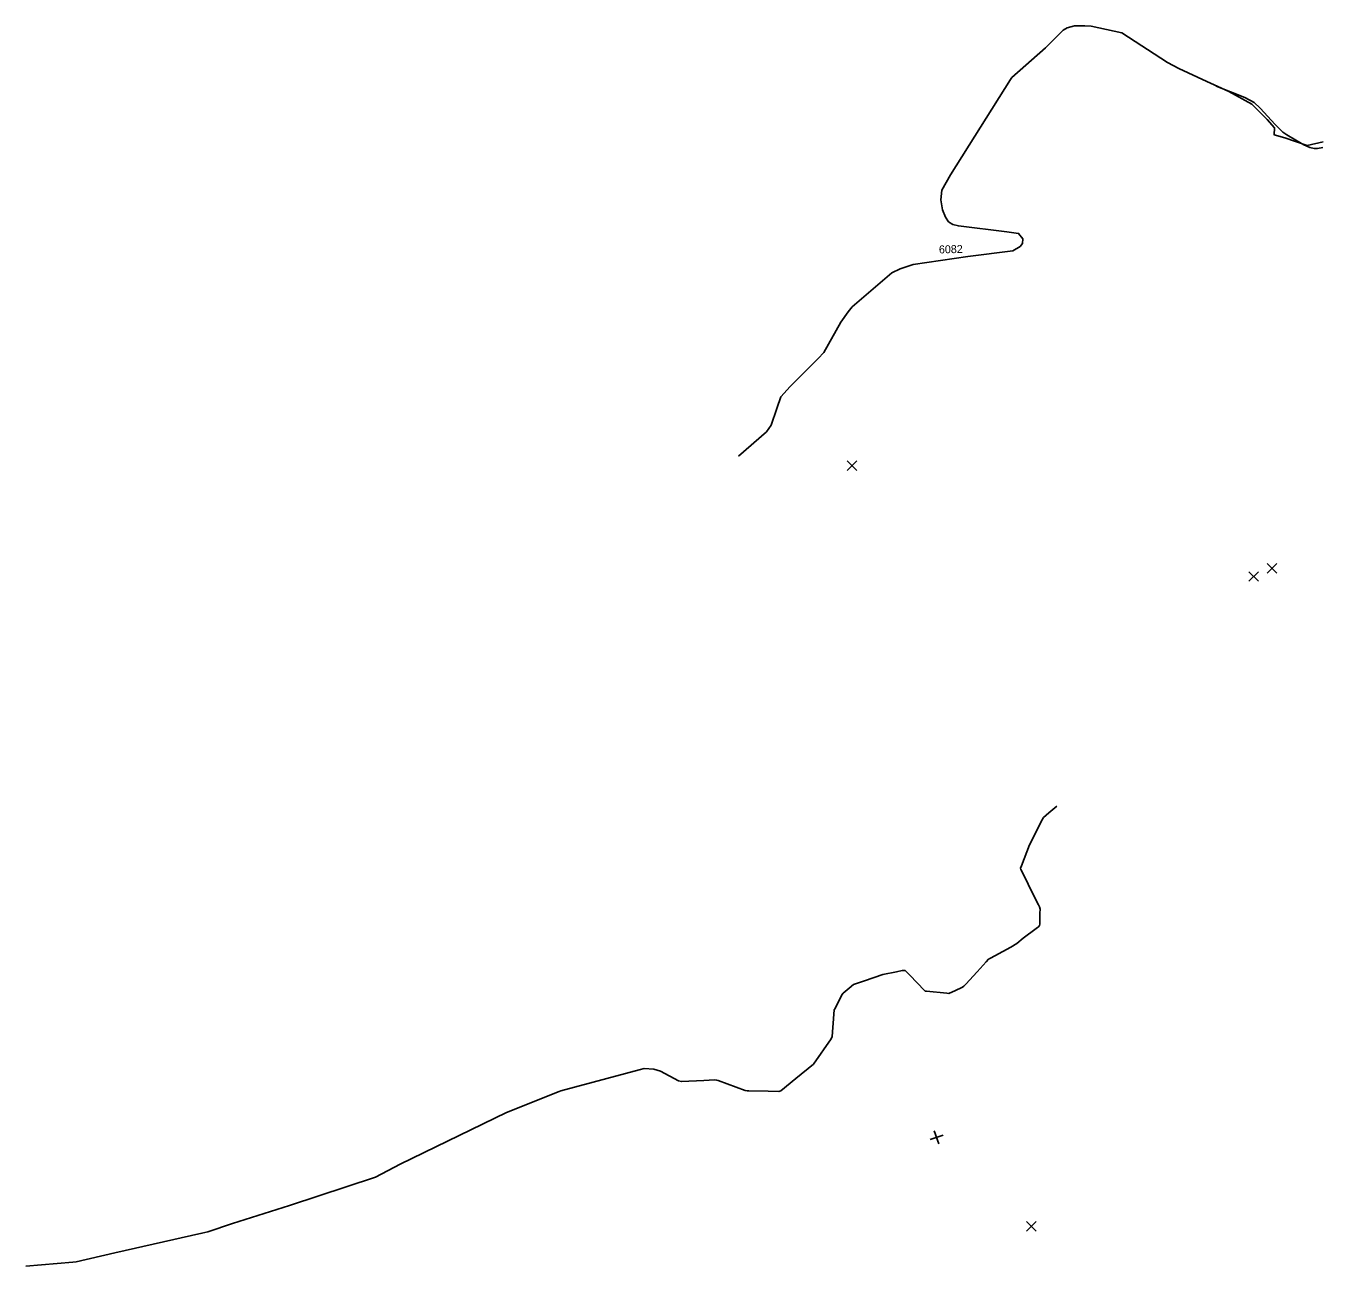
# Model space of a CAD drawing. Extents: x -446895 to -440760, y -1145420 to -1127323.
# Drawn here: x -444276 to -442655, y -1133374 to -1131824 of the extents above; entities that cross this region are included whole.
import ezdxf

# ---------------------------------------------------------------- set-up
doc = ezdxf.new("R2010")
doc.units = 0
for name, color, linetype in [('PLN_plynovod_L', 7, 'Continuous'), ('Vrstva 12', 7, 'Continuous'), ('Vrstva 200', 7, 'Continuous')]:
    doc.layers.add(name, color=color, linetype=linetype)

msp = doc.modelspace()

# ---------------------------------------------------------------- linework, layer by layer
at = {"layer": 'PLN_plynovod_L'}
msp.add_lwpolyline([(-443385.1, -1132361.7), (-443350.1, -1132331.2), (-443344.2, -1132323), (-443337.2, -1132302.1), (-443332.4, -1132287.6), (-443320.7, -1132274.8), (-443285.8, -1132239.7), (-443278.5, -1132232.3), (-443257.1, -1132194.3), (-443248.2, -1132181.2), (-443243.2, -1132175.1), (-443193.7, -1132132.4), (-443183.1, -1132127.4), (-443167, -1132122.3), (-443098.4, -1132112.3), (-443042.3, -1132105.1), (-443033.2, -1132099.8), (-443030.4, -1132095.8), (-443029.7, -1132090.3), (-443035.2, -1132083.3), (-443049.9, -1132081.2), (-443110.4, -1132074), (-443117.5, -1132072.3), (-443122.7, -1132068.7), (-443126.7, -1132063), (-443130.2, -1132053.9), (-443132.4, -1132041.5), (-443131.1, -1132029.1), (-443120.3, -1132010), (-443045.2, -1131890.8), (-443043.7, -1131888.6), (-443001.4, -1131851.4), (-442979.4, -1131829.3), (-442974.3, -1131826.4), (-442965.2, -1131824.1), (-442952.3, -1131824), (-442944.6, -1131824.4), (-442906.1, -1131832.8), (-442849.1, -1131869.7), (-442835.1, -1131877.3), (-442800.1, -1131893.4), (-442772.4, -1131906.1), (-442743.9, -1131921.6), (-442724.6, -1131940.9), (-442715.4, -1131951.4), (-442715.8, -1131960), (-442702.6, -1131964), (-442674.7, -1131973.3), (-442654.7, -1131968.9)], dxfattribs=at)
at = {"layer": 'Vrstva 12'}
for points in [[(-442788.4, -1131899.3), (-442752.4, -1131913.4), (-442740.7, -1131919.7), (-442733.4, -1131926.9), (-442714.6, -1131947.1), (-442710, -1131951.8), (-442705, -1131956.7), (-442699.8, -1131960), (-442688.8, -1131966.8), (-442678.8, -1131972.6), (-442671.4, -1131975.8), (-442665.8, -1131977.2), (-442661.5, -1131977.2), (-442655.1, -1131975.8)], [(-442987.2, -1132799.1), (-442997.2, -1132807.5), (-443004, -1132813.3), (-443006.9, -1132818.2), (-443013.7, -1132831.9), (-443021.5, -1132847.6), (-443031.5, -1132873.6), (-443032.7, -1132876.8), (-443032.5, -1132878.4), (-443030, -1132883), (-443016.4, -1132910.2), (-443010.3, -1132922.5), (-443009, -1132925.1), (-443008.3, -1132927.9), (-443008.6, -1132932.8), (-443008.8, -1132944.7), (-443008.8, -1132946.5), (-443009.2, -1132948.3), (-443010.1, -1132949.9), (-443013.2, -1132952.2), (-443029.5, -1132964.1), (-443037.3, -1132970.9), (-443044.7, -1132975.5), (-443054.8, -1132980.8), (-443064.8, -1132986.1), (-443070.1, -1132988.9), (-443072.6, -1132990.2), (-443075.7, -1132993.8), (-443086.9, -1133006.3), (-443101.2, -1133021.7), (-443103.6, -1133024.2), (-443105.2, -1133025.4), (-443114.8, -1133029.8), (-443121.4, -1133032.8), (-443122.4, -1133033.2), (-443125, -1133032.9), (-443150.3, -1133030.4), (-443151.9, -1133030.2), (-443153.4, -1133028.6), (-443161.1, -1133020.7), (-443171.9, -1133009.7), (-443177.1, -1133004.4), (-443180.5, -1133004.5), (-443187.7, -1133006.1), (-443204.6, -1133009.4), (-443227.8, -1133017.3), (-443241.4, -1133021.8), (-443246.8, -1133026.4), (-443254.2, -1133032.7), (-443255.9, -1133035.1), (-443264.4, -1133051.8), (-443265.5, -1133053.8), (-443267.2, -1133075.6), (-443268, -1133086.8), (-443269.3, -1133090.1), (-443291.6, -1133121.7), (-443313.7, -1133139.6), (-443332.4, -1133154.8), (-443334.7, -1133155.7), (-443348.2, -1133155.3), (-443372.1, -1133154.9), (-443374.3, -1133154.9), (-443376.7, -1133154.3), (-443410.4, -1133141.9), (-443412.6, -1133141.4), (-443415.2, -1133141.1), (-443428.6, -1133141.8), (-443456.6, -1133143.3), (-443460.3, -1133142.2), (-443482.8, -1133130.4), (-443491, -1133127.9), (-443502.9, -1133126.9), (-443509.5, -1133128.6), (-443607.2, -1133155.1), (-443609.1, -1133155.6), (-443674.9, -1133181.8), (-443807.9, -1133246.7), (-443838.6, -1133262.8), (-443946.2, -1133298.1), (-444017.4, -1133320.9), (-444048.5, -1133331.1), (-444055.6, -1133332.9), (-444164.4, -1133357.4), (-444213, -1133368.8), (-444216.8, -1133369.2), (-444275.6, -1133373.9)]]:
    msp.add_lwpolyline(points, dxfattribs=at)
at = {"layer": 'Vrstva 200'}
for p, q in [((-443249.5, -1132367.6), (-443237.5, -1132379.6)), ((-443237.5, -1132367.6), (-443249.5, -1132379.6)), ((-442724.5, -1132495.9), (-442712.5, -1132507.9)), ((-442712.5, -1132495.9), (-442724.5, -1132507.9)), ((-442747.4, -1132506.1), (-442735.4, -1132518.1)), ((-442735.4, -1132506.1), (-442747.4, -1132518.1)), ((-443145.6, -1133215.9), (-443129.6, -1133210.1)), ((-443140.5, -1133205), (-443134.7, -1133221)), ((-443025.3, -1133318.4), (-443013.3, -1133330.4)), ((-443013.3, -1133318.4), (-443025.3, -1133330.4))]:
    msp.add_line(p, q, dxfattribs=at)

# ---------------------------------------------------------------- texts
at = {"layer": 'PLN_plynovod_L'}
msp.add_text('6082', height=10, rotation=1.311, dxfattribs=at).set_placement((-443134.6, -1132108.4))
msp.add_text('6082', height=10, rotation=1.311, dxfattribs=at).set_placement((-443134.6, -1132108.4))

doc.saveas('drawing.dxf')
